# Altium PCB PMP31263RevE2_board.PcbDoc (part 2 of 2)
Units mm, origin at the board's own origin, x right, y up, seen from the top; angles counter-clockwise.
Board outline 111.13 x 148.59 mm, 4 copper layers (Top Layer, Layer 1, Layer 2, Bottom Layer), stack 0.603 mm thick; 138 components, 59 nets, 350 pads, 1544 vias.
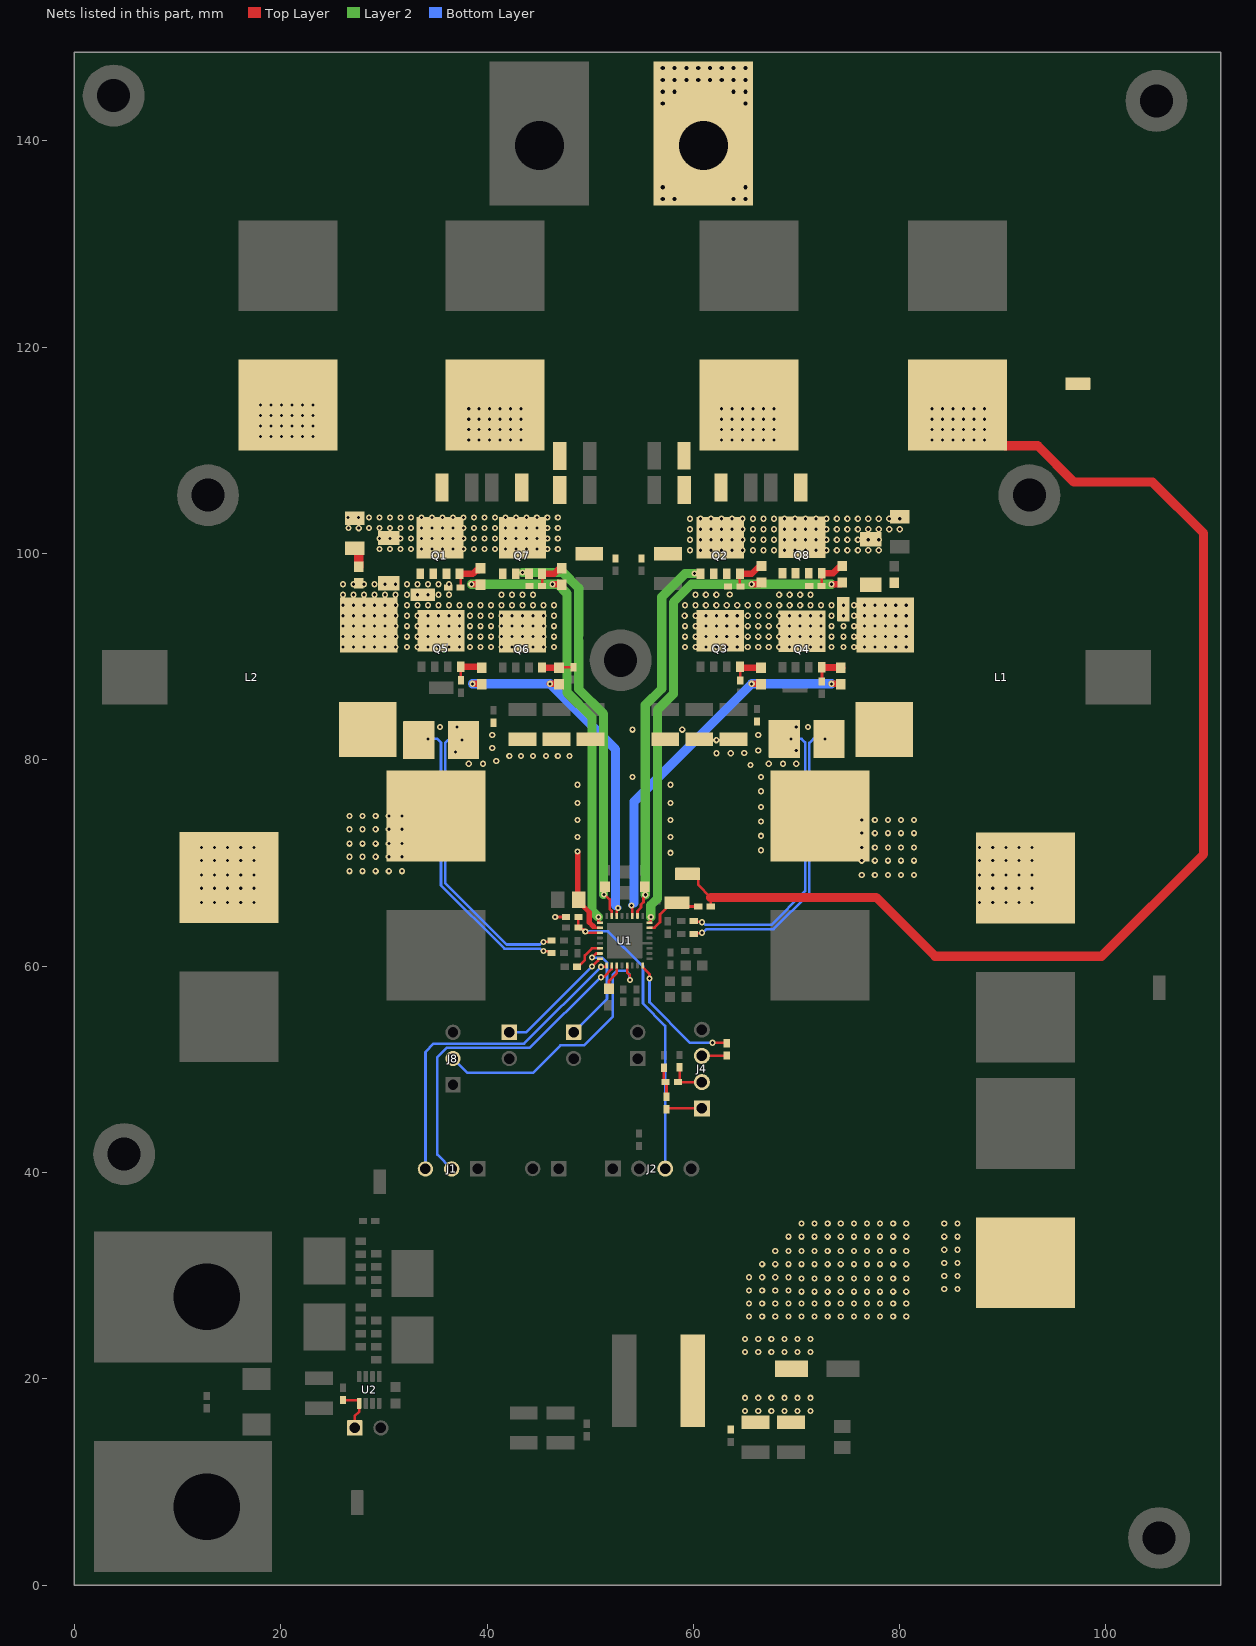
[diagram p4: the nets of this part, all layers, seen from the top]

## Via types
v1: diameter 0.6, hole 0.3, Top Layer to Bottom Layer, tented both sides, 1364 vias
v2: diameter 0.813, hole 0.406, Top Layer to Bottom Layer, 172 vias
v3: diameter 0.5, hole 0.2, Top Layer to Bottom Layer, 5 vias
v4: diameter 0.6/0.6/0.6/0.6 (per signal layer), hole 0.3, Top Layer to Bottom Layer, tented both sides, 2 vias
v5: diameter 0.6, hole 0.3, Top Layer to Bottom Layer, tented top, 1 vias

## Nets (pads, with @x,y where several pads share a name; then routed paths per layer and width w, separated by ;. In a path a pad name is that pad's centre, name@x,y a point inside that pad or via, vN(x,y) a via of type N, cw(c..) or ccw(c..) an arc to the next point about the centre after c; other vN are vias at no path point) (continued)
NetC47_1: C47.1 R33.1 | length 2
  Top Layer w0.635: R33.1@27.178,100.531 cw(c27.178,100.15) 27.45,100.417 ccw(c28.575,100.457) R33.1@27.559,99.973
  Top Layer w0.889: C47.1@27.559,98.717 R33.1@27.559,99.973
NetC52_1: C52.1 J4.2 R15.2 | length 3.8
  Top Layer w0.254: C52.1@58.674,50.2 58.674,48.93 R15.2@58.512,48.768 J4.2@60.833,48.768
NetC53_1: C53.1 R15.1 R18.1 | length 2.9
  Top Layer w0.254: C53.1@57.15,50.165 57.15,48.93 R15.1@57.312,48.768 57.404,48.676 R18.1@57.404,47.336
NetJ2_3: J2.3 R14.1 R17.2 U1.19 | length 30.8
  Top Layer w0.254: R14.1@48.86,64.77 R17.2@48.86,63.754 49.033,63.581 49.322,63.581 v1(49.53,63.373) 49.669,63.234 U1.19@50.94,63.234
  Bottom Layer w0.254: v1(49.53,63.373) 51.725,63.373 52.664,62.434 52.664,62.411 53.255,61.82 53.278,61.82 55.118,59.98 55.118,56.388 57.277,54.229 J2.3@57.277,40.386
NetJ3_1: J3.1 U1.24 | length 11.8
  Top Layer w0.254: v1(50.187,59.981) 50.767,60.561 50.767,60.732 50.769,60.734 U1.24@50.94,60.734
  Bottom Layer w0.254: J3.1@42.164,53.594 43.8,53.594 v1(50.187,59.981)
NetJ4_1: J4.1 R18.2 | length 3.5
  Top Layer w0.254: R18.2@57.404,46.136 57.496,46.228 J4.1@60.833,46.228
NetJ4_3: J4.3 R20.2 | length 2.5
  Top Layer w0.254: J4.3@60.833,51.308 63.081,51.308 R20.2@63.246,51.143
NetJ7_1: J7.1 R29.1 U2.1 | length 4.4
  Top Layer w0.254: R29.1@26.035,17.942 27.502,17.942 27.6,17.844 U2.1@27.6,17.623 27.6,16.805 27.178,16.383 J7.1@27.178,15.24
NetJ8_2: J8.2 U1.29 | length 26.4
  Top Layer w0.254: U1.29@53.59,60.084 53.59,59.403 53.848,59.145 v1(53.848,58.674)
  Bottom Layer w0.254: J8.2@36.703,51.054 38.1,49.657 44.45,49.657 47.117,52.324 49.403,52.324 52.197,55.118 52.197,59.182 52.578,59.563 53.467,59.563 53.782,59.248 53.782,58.74 v1(53.848,58.674)
NetJ9_1: J9.1 U1.23 | length 10.7
  Top Layer w0.254: v5(50.165,60.833) 50.564,61.232 50.938,61.232 U1.23@50.94,61.234
  Bottom Layer w0.254: J9.1@48.387,53.594 51.633,56.84 51.633,60.359 51.159,60.833 v5(50.165,60.833)
NetL1_2: L1.2 R3.1 R5.2 | length 29.1
  Top Layer w0.254: R5.2@60.036,63.119 60.1,63.182 60.77,63.182 v1(60.833,63.246)
  Bottom Layer w0.254: v1(60.833,63.246) 60.927,63.246 61.282,63.602 67.793,63.602 71.247,67.056 71.247,81.661 71.628,82.042 v1(72.771,82.042)
NetL2_1: L2.1 R4.2 R8.2 | length 29.8
  Top Layer w0.254: R4.2@33.141,82.042 v1(34.29,82.042) ; v1(45.466,61.468) 46.09,61.468 R8.2@46.262,61.296
  Bottom Layer w0.254: v1(34.29,82.042) 35.179,82.042 35.535,81.686 35.535,67.843 41.681,61.697 45.144,61.697 45.372,61.468 v1(45.466,61.468)
NetQ1_4: Q1.4 R27.1 R35.2 | length 3.6
  Top Layer w0.254: Q1.4@37.338,98.043 cw(c37.338,97.943) 37.438,97.943 R35.2@37.438,96.725
  Top Layer w0.635: Q1.4@37.338,98.043 38.64,98.043 39.004,98.407 39.212,98.407 39.37,98.565 R27.1@39.37,98.59
NetQ2_4: Q2.4 R21.2 R26.2 | length 3.7
  Top Layer w0.254: Q2.4@64.516,98.044 64.516,96.873 ccw(c64.564,96.873) R21.2@64.564,96.825
  Top Layer w0.635: Q2.4@64.516,98.044 65.658,98.044 66.237,98.623 66.445,98.623 66.603,98.78 R26.2@66.603,98.805
NetQ3_4: Q3.4 R9.2 R38.2 | length 3.2
  Top Layer w0.254: R38.2@64.543,87.7 64.543,88.907 cw(c64.574,88.907) Q3.4@64.574,88.938
  Top Layer w0.635: Q3.4@64.574,88.938 R9.2@66.548,88.938
NetQ4_4: Q4.4 R10.2 R39.1 | length 3.3
  Top Layer w0.254: R39.1@72.445,87.614 ccw(c72.445,87.645) 72.477,87.645 Q4.4@72.477,88.961
  Top Layer w0.635: Q4.4@72.477,88.961 74.412,88.961 R10.2@74.435,88.938
NetQ5_4: Q5.4 R12.2 R25.2 | length 3.5
  Top Layer w0.254: R25.2@37.465,87.722 Q5.4@37.465,89.026
  Top Layer w0.635: Q5.4@37.465,89.026 39.269,89.026 39.497,88.798 R12.2@39.497,88.773
NetQ6_4: Q6.4 R11.2 R24.2 | length 3.1
  Top Layer w0.254: R11.2@46.977,88.951 cw(c47.019,88.951) 47.019,88.992 R24.2@48.387,88.992
  Top Layer w0.635: Q6.4@45.339,88.963 45.352,88.951 R11.2@46.977,88.951
NetQ7_4: Q7.4 R2.1 R34.2 | length 3.3
  Top Layer w0.254: R34.2@45.323,96.857 45.339,96.857 Q7.4@45.339,98.043
  Top Layer w0.635: Q7.4@45.339,98.043 46.51,98.043 46.876,98.409 47.084,98.409 47.242,98.567 R2.1@47.242,98.592
NetQ8_4: Q8.4 R1.2 R36.2 | length 3.5
  Top Layer w0.254: R36.2@72.431,96.869 ccw(c72.431,96.891) 72.453,96.891 Q8.4@72.453,98.097
  Top Layer w0.635: Q8.4@72.453,98.097 73.544,98.097 74.07,98.623 74.278,98.623 74.435,98.78 R1.2@74.435,98.805
NetR1_1: R1.1 R26.1 U1.8 | length 50.3
  Top Layer w0.254: U1.8@55.74,64.234 55.878,64.234 55.88,64.236 v1(55.88,64.77)
  Top Layer w0.635: v1(65.659,97.028) 66.445,97.028 66.603,97.186 R26.1@66.603,97.205 ; v1(73.406,97.028) 74.278,97.028 74.435,97.186 R1.1@74.435,97.205
  Layer 2 w0.889: v1(55.88,64.77) 55.88,65.913 56.515,66.548 56.515,84.836 58.064,86.385 58.064,95.275 59.817,97.028 v1(73.406,97.028)
NetR2_2: R2.2 R27.2 U1.17 | length 44.8
  Top Layer w0.254: v1(50.8,64.77) 50.8,64.236 50.802,64.234 U1.17@50.94,64.234
  Top Layer w0.635: v1(38.481,97.028) 39.332,97.028 R27.2@39.37,96.99 ; v1(46.355,97.028) 47.205,97.028 R2.2@47.242,96.992
  Layer 2 w0.889: v1(38.481,97.028) v1(46.355,97.028) 46.863,97.028 47.752,96.139 47.752,86.538 50.165,84.125 50.165,65.405 v1(50.8,64.77)
NetR9_1: R9.1 R10.1 U1.11 | length 36.9
  Top Layer w0.254: v1(53.996,65.892) 53.996,65.798 54.09,65.704 U1.11@54.09,64.884
  Top Layer w0.635: v1(65.659,87.376) 66.51,87.376 R9.1@66.548,87.338 ; v1(73.406,87.376) 74.257,87.376 R10.1@74.295,87.338
  Bottom Layer w0.635: v1(53.996,65.892) 54.245,66.14
  Bottom Layer w0.889: 54.245,66.14 54.245,75.962 v1(65.659,87.376) v1(73.406,87.376)
NetR11_1: R11.1 R12.1 U1.14 | length 34.6
  Top Layer w0.254: U1.14@52.59,64.884 52.59,65.544 v1(52.705,65.659)
  Top Layer w0.635: v1(38.608,87.376) 39.459,87.376 R12.1@39.497,87.338 ; v1(46.101,87.376) 46.952,87.376 R11.1@46.99,87.338
  Bottom Layer w0.635: 52.451,65.913 v1(52.705,65.659)
  Bottom Layer w0.889: v1(38.608,87.376) v1(46.101,87.376) 52.451,81.026 52.451,65.913
NetR13_1: R13.1 TP2.1 U1.7 | length 6.4
  Top Layer w0.254: U1.7@55.74,63.734 55.742,63.736 56.237,63.736 56.769,64.268 56.769,65.024 58.293,66.548 TP2.1@58.293,66.562 ; TP2.1@58.42,66.167 58.801,65.786 R13.1@60.487,65.786
NetR19_2: R19.2 U1.27 | length 2.6
  Top Layer w0.254: R19.2@51.816,57.848 51.824,57.856 51.824,58.555 52.59,59.321 U1.27@52.59,60.084
NetR20_1: R20.1 U1.32 | length 13
  Top Layer w0.254: U1.32@55.09,60.084 55.09,59.913 55.753,59.25 v1(55.753,58.801) ; v1(61.849,52.578) 63.081,52.578 R20.1@63.246,52.743
  Bottom Layer w0.254: v1(55.753,58.801) 55.753,56.515 59.69,52.578 v1(61.849,52.578)
NetR37_1: R37.1 U1.22 | length 3.2
  Top Layer w0.254: R37.1@48.733,59.944 48.833,59.944 49.491,60.602 49.491,61.058 50.167,61.734 U1.22@50.94,61.734
SCL: J1.2 U1.26 | length 32.2
  Top Layer w0.254: v1(51.054,58.928) 51.12,58.994 51.367,58.994 52.09,59.717 U1.26@52.09,60.084
  Bottom Layer w0.254: J1.2@36.572,40.346 35.179,41.739 35.179,51.181 36.081,52.083 44.142,52.083 50.986,58.928 v1(51.054,58.928)
SDA: J1.3 U1.25 | length 32.5
  Top Layer w0.254: v1(51.054,59.944) 51.588,59.944 51.59,59.946 U1.25@51.59,60.084
  Bottom Layer w0.254: J1.3@34.032,40.346 34.032,51.685 34.837,52.49 43.6,52.49 v1(51.054,59.944)
SW1: C46.2 D3.2 L1.1 Q2.1 Q2.2 Q2.3 Q3.5 Q4.5 Q8.1 Q8.2 Q8.3 R21.1 R30.2 R36.1 TP3.1 U1.10 | length 36.8
  Top Layer w0.254: U1.10@54.59,64.884 54.59,65.358 54.931,65.699 54.931,65.972 54.999,66.04 55.172,66.213 55.172,66.661 55.347,66.835 v1(55.347,66.929) 55.347,67.66 R30.2@55.298,67.709
  Layer 2 w0.889: v1(55.347,66.929) 55.347,85.319 56.935,86.907 56.935,95.797 59.207,98.069 v1(60.118,98.069)
  other v1: 59.182,90.932 60.198,90.932 61.214,90.932 62.23,90.932 63.246,90.932 64.262,90.932 65.278,90.932 66.294,90.932 67.31,90.932 68.326,90.932 69.342,90.932 70.358,90.932 71.374,90.932 72.39,90.932 73.406,90.932 74.549,90.932 75.565,90.932 76.581,90.932 77.597,90.932 78.613,90.932 79.629,90.932 80.645,90.932 59.182,91.948 60.198,91.948 61.214,91.948 62.23,91.948 63.246,91.948 64.262,91.948 65.278,91.948 66.294,91.948 67.31,91.948 68.326,91.948 69.342,91.948 70.358,91.948 71.374,91.948 72.39,91.948 73.406,91.948 74.549,91.948 75.565,91.948 76.581,91.948 77.597,91.948 78.613,91.948 79.629,91.948 80.645,91.948 59.182,92.964 60.198,92.964 61.214,92.964 62.23,92.964 63.246,92.964 64.262,92.964 65.278,92.964 66.294,92.964 67.31,92.964 68.326,92.964 69.342,92.964 70.358,92.964 71.374,92.964 72.39,92.964 73.406,92.964 74.549,92.964 75.565,92.964 76.581,92.964 77.597,92.964 78.613,92.964 79.629,92.964 80.645,92.964 59.161,93.979 60.198,93.98 61.214,93.98 62.23,93.98 63.246,93.98 64.262,93.98 65.278,93.98 66.294,93.98 67.31,93.98 68.326,93.98 69.342,93.98 70.358,93.98 71.374,93.98 72.39,93.98 73.406,93.98 74.549,93.98 75.565,93.98 76.581,93.98 77.597,93.98 78.613,93.98 79.629,93.98 80.645,93.98 59.203,94.994 60.198,94.996 61.214,94.996 62.23,94.996 63.246,94.996 64.262,94.996 65.278,94.996 66.294,94.996 67.31,94.996 68.326,94.996 69.342,94.996 70.358,94.996 71.374,94.996 72.39,94.996 73.406,94.996 74.549,94.996 75.565,94.996 76.581,94.996 77.597,94.996 78.613,94.996 79.629,94.996 80.645,94.996 60.198,96.012 61.214,96.012 62.23,96.012 63.53,96.024 68.326,96.012 69.342,96.012 70.358,96.012 71.374,96.012
SW2: C47.2 D2.2 L2.2 Q1.1 Q1.2 Q1.3 Q5.5 Q6.5 Q7.1 Q7.2 Q7.3 R31.1 R34.1 R35.1 TP5.1 U1.15 | length 40
  Top Layer w0.254: R31.1@51.181,67.508 R31.1@51.181,67.602 ; v1(51.338,66.951) 51.338,67.594 R31.1@51.435,67.691 ; v1@51.435,66.929 51.881,66.483 51.881,66.04 51.881,65.83 51.892,65.819 51.892,65.557 52.09,65.36 ; U1.15@52.095,64.853 52.095,65.354
  Layer 2 w0.889: v1(43.434,98.171) 47.371,98.171 48.895,96.647 48.895,92.208 cw(c48.006,92.208) 48.892,92.137 ccw(c52.832,91.821) 48.892,91.503 cw(c48.006,91.434) 48.895,91.434 48.895,86.868 51.308,84.455 v1@51.308,66.951
  other v1: 26.035,90.932 27.051,90.932 28.067,90.932 29.083,90.932 30.099,90.932 31.115,90.932 32.258,90.932 33.274,90.932 34.29,90.932 35.306,90.932 36.322,90.932 37.338,90.932 38.354,90.932 39.37,90.932 40.386,90.932 41.402,90.932 42.418,90.932 43.434,90.932 44.45,90.932 45.466,90.932 46.482,90.932 26.035,91.948 27.051,91.948 28.067,91.948 29.083,91.948 30.099,91.948 31.115,91.948 32.258,91.948 33.274,91.948 34.29,91.948 35.306,91.948 36.322,91.948 37.338,91.948 38.354,91.948 39.37,91.948 40.386,91.948 41.402,91.948 42.418,91.948 43.434,91.948 44.45,91.948 45.466,91.948 46.482,91.948 26.035,92.964 27.051,92.964 28.067,92.964 29.083,92.964 30.099,92.964 31.115,92.964 32.258,92.964 33.274,92.964 34.29,92.964 35.306,92.964 36.322,92.964 37.338,92.964 38.354,92.964 39.37,92.964 40.386,92.964 41.402,92.964 42.418,92.964 43.434,92.964 44.45,92.964 45.466,92.964 46.482,92.964 26.035,93.98 27.051,93.98 28.067,93.98 29.083,93.98 30.099,93.98 31.115,93.98 32.258,93.98 33.274,93.98 34.29,93.98 35.306,93.98 36.322,93.98 37.338,93.98 38.354,93.98 39.37,93.98 40.386,93.98 41.402,93.98 42.418,93.98 43.434,93.98 44.45,93.98 45.466,93.98 46.482,93.98 26.035,94.996 27.051,94.996 28.067,94.996 29.083,94.996 30.099,94.996 31.115,94.996 32.258,94.996 33.274,94.996 34.29,94.996 35.306,94.996 36.322,94.996 37.338,94.996 38.354,94.996 39.37,94.996 40.386,94.996 41.402,94.996 42.418,94.996 43.434,94.996 44.45,94.996 45.466,94.996 46.482,94.996 26.035,96.012 27.051,96.012 28.067,96.012 29.083,96.012 30.099,96.012 31.115,96.012 32.258,96.012 33.274,96.012 34.29,96.012 35.306,96.012 36.322,96.012 41.402,96.012 42.418,96.012 43.434,96.012 44.45,96.012 26.035,97.028 27.051,97.028 28.067,97.028 29.083,97.028 30.099,97.028 31.115,97.028 32.258,97.028 33.274,97.028 34.29,97.028 35.306,97.028 36.322,97.028
Vboost: C16.1 C17.1 C18.1 C19.1 C20.1 C21.1 C22.1 C23.1 C24.1 C25.1 C48.1 C49.1 C50.1 C51.1 C54.1 C55.1 D2.1 D3.1 Q1.5 Q2.5 Q7.5 Q8.5 R13.2 R32.2 R33.2 T2.1 TP1.1 TP8.1 | length 125.5
  Top Layer w0.254: TP1.1@59.436,68.961 59.988,68.961 60.461,68.488 60.461,67.901 61.687,66.675 R13.2@61.687,65.786
  Top Layer w0.889: 61.687,66.675 77.724,66.675 83.439,60.96 99.568,60.96 109.474,70.866 109.474,101.981 104.521,106.934 96.903,106.934 93.384,110.452 90.237,110.452 88.819,111.87 C19.1@88.819,112.314 ; C19.1@86.082,113.924 C19.1@87.098,112.908 ; C19.1@87.012,113.838 C19.1@87.52,113.33 ; v1(88.236,110.998) 88.236,111.77 C19.1@87.098,112.908 ; C19.1@88.536,112.314 88.028,112.822 C19.1@87.52,113.33 ; C19.1@87.098,112.908 C19.1@85.598,114.408 86.442,114.408 C19.1@87.52,113.33
  other v1: 59.69,100.33 60.706,100.33 61.722,100.33 62.738,100.33 63.754,100.33 64.77,100.33 65.786,100.33 66.802,100.33 67.818,100.33 68.834,100.33 69.85,100.33 70.866,100.33 71.882,100.33 72.898,100.33 73.914,100.33 74.93,100.33 75.946,100.33 76.962,100.33 77.978,100.33 29.591,100.457 30.607,100.457 31.623,100.457 32.639,100.457 33.655,100.457 34.671,100.457 35.687,100.457 36.703,100.457 37.719,100.457 38.735,100.457 39.751,100.457 40.767,100.457 41.783,100.457 42.799,100.457 43.815,100.457 44.831,100.457 45.847,100.457 46.863,100.457 59.69,101.346 60.706,101.346 61.722,101.346 62.738,101.346 63.754,101.346 64.77,101.346 65.786,101.346 66.802,101.346 67.818,101.346 68.834,101.346 69.85,101.346 70.866,101.346 71.882,101.346 72.898,101.346 73.914,101.346 74.93,101.346 75.946,101.346 76.962,101.346 77.978,101.346 29.591,101.473 30.607,101.473 31.623,101.473 32.639,101.473 33.655,101.473 34.671,101.473 35.687,101.473 36.703,101.473 37.719,101.473 38.735,101.473 39.751,101.473 40.767,101.473 41.783,101.473 42.799,101.473 43.815,101.473 44.831,101.473 45.847,101.473 46.863,101.473 59.69,102.362 60.706,102.362 61.722,102.362 62.738,102.362 63.754,102.362 64.77,102.362 65.786,102.362 66.802,102.362 67.818,102.362 68.834,102.362 69.85,102.362 70.866,102.362 71.882,102.362 72.898,102.362 73.914,102.362 74.93,102.362 75.946,102.362 76.962,102.362 77.978,102.362 78.994,102.362 80.01,102.362 26.568,102.475 27.571,102.467 28.575,102.489 29.591,102.489 30.607,102.489 31.623,102.489 32.639,102.489 33.655,102.489 34.671,102.489 35.687,102.489 36.703,102.489 37.719,102.489 38.735,102.489 39.751,102.489 40.767,102.489 41.783,102.489 42.799,102.489 43.815,102.489 44.831,102.489 45.847,102.489 46.863,102.489 59.69,103.378 60.706,103.378 61.722,103.378 62.738,103.378 63.754,103.378 64.77,103.378 65.786,103.378 66.802,103.378 67.818,103.378 68.834,103.378 69.85,103.378 70.866,103.378 71.882,103.378 72.898,103.378 73.914,103.378 74.93,103.378 75.946,103.378 76.962,103.378 77.978,103.378 78.994,103.378 80.01,103.378 26.543,103.505 27.559,103.505 28.575,103.505 29.591,103.505 30.607,103.505 31.623,103.505 32.639,103.505 33.655,103.505 34.671,103.505 35.687,103.505 36.703,103.505 37.719,103.505 38.735,103.505 39.751,103.505 40.767,103.505 41.783,103.505 42.799,103.505 43.815,103.505 44.831,103.505 45.847,103.505 46.863,103.505 38.227,110.998 39.243,110.998 40.259,110.998 41.275,110.998 42.291,110.998 43.307,110.998 62.738,110.998 63.754,110.998 64.77,110.998 65.786,110.998 66.802,110.998 67.818,110.998 83.156,110.998 84.172,110.998 85.188,110.998 86.204,110.998 87.22,110.998 18.034,111.36 19.05,111.36 20.066,111.36 21.082,111.36 22.098,111.36 23.114,111.36 38.227,112.014 39.243,112.014 40.259,112.014 41.275,112.014 42.291,112.014 43.307,112.014 62.738,112.014 63.754,112.014 64.77,112.014 65.786,112.014 66.802,112.014 67.818,112.014 83.156,112.014 84.172,112.014 85.188,112.014 86.204,112.014 87.22,112.014 88.236,112.014 18.034,112.376 19.05,112.376 20.066,112.376 21.082,112.376 22.098,112.376 23.114,112.376 38.227,113.03 39.243,113.03 40.259,113.03 41.275,113.03 42.291,113.03 43.307,113.03 62.738,113.03 63.754,113.03 64.77,113.03 65.786,113.03 66.802,113.03 67.818,113.03 83.156,113.03 84.172,113.03 85.188,113.03 86.204,113.03 87.22,113.03 88.236,113.03 18.034,113.392 19.05,113.392 20.066,113.392 21.082,113.392 22.098,113.392 23.114,113.392 38.227,114.046 39.243,114.046 40.259,114.046 41.275,114.046 42.291,114.046 43.307,114.046 62.738,114.046 63.754,114.046 64.77,114.046 65.786,114.046 66.802,114.046 67.818,114.046 83.156,114.046 84.172,114.046 85.188,114.046 86.204,114.046 87.22,114.046 88.236,114.046 18.034,114.408 19.05,114.408 20.066,114.408 21.082,114.408 22.098,114.408 23.114,114.408
  other v2: 57.046,134.366 58.189,134.366 63.904,134.366 65.047,134.366 57.046,135.509 65.047,135.509 57.046,143.637 65.047,143.637 57.046,144.78 58.189,144.78 63.904,144.78 65.047,144.78 57.046,145.923 58.189,145.923 59.332,145.923 60.475,145.923 61.618,145.923 62.761,145.923 63.904,145.923 65.047,145.923 57.046,147.066 58.189,147.066 59.332,147.066 60.475,147.066 61.618,147.066 62.761,147.066 63.904,147.066 65.047,147.066
VIN_FLT: C1.1 C2.1 C3.1 C4.1 C5.1 C6.1 C7.1 C8.1 C9.1 C10.1 C11.1 C12.1 C13.1 C14.1 C15.1 C30.1 C37.1 C43.1 L3.2 R3.2 R4.1 R6.2 R7.2 R14.2 U1.18 | length 68.9
  Top Layer w0.254: R4.1@38.614,81.915 R4.1@38.741,82.042 ; v1(45.466,62.357) 46.136,62.357 R7.2@46.263,62.484 ; v1(46.609,64.77) R14.2@47.66,64.77 ; 50.272,63.734 U1.18@50.94,63.734 ; R6.2@60.036,64.389 60.1,64.325 60.77,64.325 v1(60.833,64.262)
  Top Layer w0.508: v1(48.768,71.12) 48.786,71.102 48.786,66.967 48.62,66.802 48.514,66.802 C30.1@48.895,66.421 48.895,66.256 49.911,65.24 49.911,64.262 50.292,63.881
  Top Layer w0.635: v4(37.592,81.915) R4.1@38.614,81.915 ; R3.2@68.193,82.042 v4(69.469,82.042)
  Bottom Layer w0.254: v4(37.592,81.915) 36.195,81.915 35.941,81.661 35.941,68.072 41.91,62.103 45.118,62.103 45.372,62.357 v1(45.466,62.357) ; v1(60.833,64.262) 60.927,64.262 61.181,64.008 67.564,64.008 70.841,67.285 70.841,81.686 70.485,82.042 v4(69.469,82.042)
  other v1: 65.024,16.891 66.294,16.891 67.564,16.891 68.834,16.891 70.104,16.891 71.374,16.891 65.024,18.161 66.294,18.161 67.564,18.161 68.834,18.161 70.104,18.161 71.374,18.161 65.024,22.606 66.294,22.606 67.564,22.606 68.834,22.606 70.104,22.606 71.374,22.606 65.024,23.876 66.294,23.876 67.564,23.876 68.834,23.876 70.104,23.876 71.374,23.876 65.405,26.035 66.675,26.035 67.945,26.035 69.215,26.035 70.485,26.035 71.755,26.035 73.025,26.035 74.295,26.035 75.565,26.035 76.835,26.035 78.105,26.035 79.375,26.035 80.645,26.035 65.405,27.305 66.675,27.305 67.945,27.305 69.215,27.305 70.485,27.305 71.755,27.305 73.025,27.305 74.295,27.305 75.565,27.305 76.835,27.305 78.105,27.305 79.375,27.305 80.645,27.305 70.485,28.448 71.755,28.448 73.025,28.448 74.295,28.448 75.565,28.448 76.835,28.448 78.105,28.448 79.375,28.448 80.645,28.448 65.405,28.575 66.675,28.575 67.945,28.575 69.215,28.575 84.328,28.702 85.598,28.702 70.485,29.718 71.755,29.718 73.025,29.718 74.295,29.718 75.565,29.718 76.835,29.718 78.105,29.718 79.375,29.718 80.645,29.718 65.405,29.845 66.675,29.845 67.945,29.845 69.215,29.845 84.328,29.972 85.598,29.972 66.675,31.115 67.945,31.115 69.215,31.115 70.485,31.115 71.755,31.115 73.025,31.115 74.295,31.115 75.565,31.115 76.835,31.115 78.105,31.115 79.375,31.115 80.645,31.115 84.328,31.242 85.598,31.242 67.945,32.385 69.215,32.385 70.485,32.385 71.755,32.385 73.025,32.385 74.295,32.385 75.565,32.385 76.835,32.385 78.105,32.385 79.375,32.385 80.645,32.385 84.328,32.512 85.598,32.512 69.215,33.782 70.485,33.782 71.755,33.782 73.025,33.782 74.295,33.782 75.565,33.782 76.835,33.782 78.105,33.782 79.375,33.782 80.645,33.782 84.328,33.782 85.598,33.782 70.485,35.052 71.755,35.052 73.025,35.052 74.295,35.052 75.565,35.052 76.835,35.052 78.105,35.052 79.375,35.052 80.645,35.052 84.328,35.052 85.598,35.052 12.319,66.167 13.589,66.167 14.859,66.167 16.129,66.167 17.399,66.167 87.757,66.167 89.027,66.167 90.297,66.167 91.567,66.167 92.837,66.167 12.319,67.564 13.589,67.564 14.859,67.564 16.129,67.564 17.399,67.564 87.757,67.564 89.027,67.564 90.297,67.564 91.567,67.564 92.837,67.564 12.319,68.834 13.589,68.834 14.859,68.834 16.129,68.834 17.399,68.834 76.327,68.834 77.597,68.834 78.867,68.834 80.137,68.834 81.407,68.834 87.757,68.834 89.027,68.834 90.297,68.834 91.567,68.834 92.837,68.834 26.67,69.215 27.94,69.215 29.21,69.215 30.48,69.215 31.75,69.215 12.319,70.231 13.589,70.231 14.859,70.231 16.129,70.231 17.399,70.231 76.327,70.231 77.597,70.231 78.867,70.231 80.137,70.231 81.407,70.231 87.757,70.231 89.027,70.231 90.297,70.231 91.567,70.231 92.837,70.231 26.67,70.612 27.94,70.612 29.21,70.612 30.48,70.612 31.75,70.612 57.785,70.993 66.548,71.247 12.319,71.501 13.589,71.501 14.859,71.501 16.129,71.501 17.399,71.501 76.327,71.501 77.597,71.501 78.867,71.501 80.137,71.501 81.407,71.501 87.757,71.501 89.027,71.501 90.297,71.501 91.567,71.501 92.837,71.501 26.67,71.882 27.94,71.882 29.21,71.882 30.48,71.882 31.75,71.882 48.768,72.517 57.785,72.517 66.548,72.644 76.327,72.898 77.597,72.898 78.867,72.898 80.137,72.898 81.407,72.898 26.67,73.279 27.94,73.279 29.21,73.279 30.48,73.279 31.75,73.279 66.548,74.041 48.768,74.168 57.785,74.168 76.327,74.168 77.597,74.168 78.867,74.168 80.137,74.168 81.407,74.168 26.67,74.549 27.94,74.549 29.21,74.549 30.48,74.549 31.75,74.549 66.548,75.438 48.768,75.819 57.785,75.819 66.548,76.962 48.768,77.597 57.785,77.597 54.102,78.359 66.548,78.359 65.532,79.502 38.227,79.629 39.624,79.629 67.31,79.629 68.707,79.629 69.977,79.629 40.894,79.883 42.164,80.391 43.307,80.391 44.45,80.391 45.72,80.391 46.863,80.391 48.006,80.391 62.244,80.649 63.627,80.645 64.936,80.657 36.957,80.772 66.294,80.899 69.977,80.899 40.513,81.153 62.23,81.915 40.513,82.423 66.294,82.423 54.102,82.931 58.928,82.931 35.433,83.185 37.084,83.185 69.977,83.185 71.12,83.185
pads on no net: L1.3 L2.3 U2.3

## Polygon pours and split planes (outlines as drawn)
GND on Top Layer "NONET_L01_P-001" (solid, pour order 51): 21.412,38.71 25.197,42.494 29.769,42.494 33.553,38.71 110.363,38.71 110.363,59.69 82.931,59.69 76.962,65.659 50.038,65.659 48.514,67.183 45.339,67.183 43.815,65.659 30.226,65.659 24.13,59.563 1.397,59.563 1.397,38.71
NetC45_1 on Top Layer "NONET_L01_P-001" (solid, pour order 37): 27.356,32.588 27.178,32.41 27.178,22.733 27.305,22.606 29.718,22.606 29.845,22.733 29.845,32.461 29.718,32.588
GND on Top Layer "NONET_L01_P-001" (solid, pour order 17): 41.529,84.074 41.134,84.469 36.054,84.469 32.004,88.519 32.004,89.408 32.258,89.662 46.863,89.662 47.498,90.297 47.498,95.504 48.514,96.52 48.514,98.298 48.768,98.552 58.674,98.552 59.055,98.171 59.055,96.52 58.039,95.504 58.039,90.297 58.674,89.662 71.755,89.662 72.263,89.154 72.263,85.217 71.755,84.709 65.726,84.709 65.091,84.074
SW2 on Top Layer "NONET_L01_P-001" (solid, pour order 3): 30.353,90.424 30.353,98.552 36.449,98.552 cw(c36.449,98.425) 36.576,98.425 36.576,96.774 ccw(c37.592,96.774) 37.592,95.758 39.497,95.758 ccw(c39.497,97.155) 40.894,97.155 40.894,98.425 cw(c41.148,98.425) 41.148,98.679 44.323,98.679 cw(c44.323,98.425) 44.577,98.425 44.577,96.647 ccw(c45.593,96.774) 45.72,95.758 cw(c45.812,94.658) 46.863,94.996 46.863,90.932 cw(c46.355,90.932) 46.355,90.424
Vboost on Top Layer "NONET_L01_P-001" (solid, pour order 10): 36.449,99.441 25.654,99.441 15.367,109.728 15.367,118.491 36.449,118.491
SW2 on Top Layer "NONET_L01_P-001" (solid, pour order 76): 31.242,98.552 30.489,98.552 ccw(c30.489,96.384) 28.956,97.917 cw(c28.343,98.53) 28.343,97.663 26.457,97.663 ccw(c26.457,96.574) 25.369,96.574 25.369,90.862 ccw(c25.807,90.862) 25.807,90.424 31.115,90.424 ccw(c31.115,90.551) 31.242,90.551
VIN_FLT on Top Layer "NONET_L01_P-001" (solid, pour order 48): 65.405,73.914 104.267,73.914 105.029,73.152 105.029,67.056 98.933,60.96 83.185,60.96 77.724,66.421 64.897,66.421 60.833,70.485
GND on Top Layer "NONET_L01_P-001" (solid, pour order 47): 98.044,147.828 110.363,135.509 110.363,120.777 109.728,120.142 15.748,120.142 14.035,118.429 14.035,107.507 10.795,104.267 3.81,104.267 1.778,106.299 1.778,134.493 15.113,147.828
Vboost on Top Layer "NONET_L01_P-001" (solid, pour order 19): 48.514,110.109 48.514,111.252 49.022,111.76 57.277,111.76 57.658,111.379 57.658,104.14 57.023,103.505 57.023,103.251 63.5,103.251 63.983,103.734 63.983,118.745 45.339,118.745 45.339,110.109
VIN_FLT on Top Layer "NONET_L01_P-001" (solid, pour order 18): 40.894,83.82 41.402,83.312 65.151,83.312 65.786,83.947 71.755,83.947 72.136,83.566 72.136,80.01 72.898,79.248 76.835,79.248 83.185,72.898 83.185,70.231 40.259,70.231 30.353,70.231 29.591,70.993 29.591,78.867 29.972,79.248 34.163,79.248 34.798,79.883 34.798,83.439 35.179,83.82
NetL2_1 on Top Layer "NONET_L01_P-001" (solid, pour order 15): 31.623,87.63 34.29,84.963 34.29,80.264 33.909,79.883 25.273,79.883 24.892,80.264 24.892,87.249 25.273,87.63
Vboost on Top Layer "NONET_L01_P-001" (solid, pour order 8): 35.814,99.441 37.973,99.441 38.65,99.949 39.963,99.949 40.64,99.441 45.974,99.441 46.482,99.949 47.879,99.949 48.514,99.314 65.405,99.314 66.04,99.949 67.183,99.949 67.818,99.314 72.898,99.314 73.533,99.949 82.169,99.949 98.425,116.205 98.425,118.491 69.088,118.491 69.088,104.394 68.453,103.759 53.721,103.759 35.814,103.759
GND on Top Layer "NONET_L01_P-001" (solid, pour order 5): 68.326,108.204 cw(c68.326,108.077) 68.453,108.077 68.453,104.775 cw(c68.326,104.775) 68.326,104.648 64.77,104.648 cw(c64.77,104.775) 64.643,104.775 64.643,108.077 cw(c64.77,108.077) 64.77,108.204
GND on Top Layer "NONET_L01_P-001" (solid, pour order 0): 56.896,111.125 cw(c56.896,110.871) 57.15,110.871 57.15,104.521 cw(c56.897,104.52) 56.896,104.267 55.372,104.267 cw(c55.372,104.521) 55.118,104.521 55.118,110.871 cw(c55.372,110.871) 55.372,111.125
Vboost on Top Layer "NONET_L01_P-001" (solid, pour order 11): 37.465,104.14 41.783,104.14 42.037,104.394 42.037,108.458 41.656,108.839 40.259,108.839 40.259,110.363 41.021,111.125 48.514,111.125 48.514,104.14 50.673,101.981 37.465,101.981
Vboost on Top Layer "NONET_L01_P-001" (solid, pour order 12): 40.513,108.839 37.211,108.839 36.83,108.458 36.83,104.521 37.211,104.14 37.465,104.14 37.465,103.124 35.687,103.124 35.687,110.363 36.068,110.744 40.64,110.744
NetL1_2 on Top Layer "NONET_L01_P-001" (solid, pour order 16): 76.581,87.63 72.671,83.72 72.671,80.264 73.052,79.883 81.688,79.883 82.069,80.264 82.069,87.249 81.688,87.63
Vboost on Top Layer "NONET_L01_P-001" (solid, pour order 54): 109.728,119.253 110.363,118.618 110.363,108.458 109.728,107.823 87.249,107.823 79.502,115.57 15.367,115.57 15.367,118.872 15.748,119.253
VIN_FLT on Top Layer "NONET_L01_P-001" (solid, pour order 65): 69.85,35.687 58.801,24.638 58.801,15.24 59.055,14.986 71.12,14.986 71.882,15.748 71.882,21.971 72.898,22.987 93.472,22.987 97.409,26.924 97.409,35.306 97.028,35.687
GND on Top Layer "NONET_L01_P-001" (solid, pour order 66): 1.397,16.51 2.159,17.272 21.336,17.272 21.971,17.907 32.766,17.907 36.068,14.605 50.038,14.605 52.07,12.573 61.849,12.573 63.246,13.97 76.2,13.97 76.835,14.605 76.835,21.59 77.343,22.098 93.98,22.098 98.171,26.289 98.171,35.56 96.266,37.465 96.266,38.735 110.363,38.735 110.363,3.302 108.077,1.016 2.032,1.016 1.397,1.651
SW1 on Top Layer "NONET_L01_P-001" (solid, pour order 1): 81.407,90.424 ccw(c81.407,90.678) 81.661,90.678 81.661,95.631 ccw(c81.153,95.631) 81.153,96.139 72.263,96.139 cw(c72.263,96.774) 71.628,96.774 71.628,98.552 ccw(c71.501,98.552) 71.501,98.679 68.326,98.679 ccw(c68.326,98.425) 68.072,98.425 68.072,97.155 cw(c66.802,97.155) 66.802,95.885 64.643,95.885 cw(c64.579,96.71) 63.754,96.647 63.754,98.552 ccw(c63.627,98.552) 63.627,98.679 60.198,98.679 ccw(c60.198,98.298) 59.817,98.298 59.817,96.139 cw(c59.182,96.139) 59.182,95.504 ccw(c59.182,94.996) 58.674,94.996 58.674,90.932 ccw(c59.182,90.932) 59.182,90.424
Vboost on Top Layer "NONET_L01_P-001" (solid, pour order 14): 70.358,110.744 70.358,108.458 69.088,108.458 68.707,108.839 64.389,108.839 63.627,108.077 62.738,108.077 62.738,110.744
Vboost on Top Layer "NONET_L01_P-001" (solid, pour order 20): 69.018,104.092 64.31,104.092 63.373,105.029 63.373,103.378 68.961,103.378 68.961,103.489 69.018,103.547
AGND on Top Layer "NONET_L01_P-001" (solid, pour order 22): 58.547,57.785 57.912,57.15 50.8,57.15 48.26,59.69 48.26,63.881 48.006,64.135 45.085,64.135 44.45,63.5 44.45,59.055 52.578,50.927 59.182,50.927 62.103,53.848 62.103,61.849 61.468,62.484 58.547,62.484
VIN_FLT on Top Layer "NONET_L01_P-001" (solid, pour order 30): 1.524,73.724 1.524,60.452 24.13,60.452 29.972,66.294 43.561,66.294 47.879,70.612 47.879,77.724 46.355,79.248 29.972,79.248 24.448,73.724
NetC40_1 on Top Layer "NONET_L01_P-001" (solid, pour order 38): 36.913,15.411 31.877,20.447 31.287,20.447 30.608,21.126 30.608,34.121 30.952,34.442 52.629,34.442 54.738,32.333 54.738,15.665 54.484,15.411
NetC38_1 on Top Layer "NONET_L01_P-001" (solid, pour order 57): 19.685,34.417 25.73,40.462 30.353,40.462 30.607,40.208 30.607,37.922 29.413,36.728 26.899,36.728 26.416,36.246 26.416,19.431 26.67,19.177 26.416,18.923 21.717,18.923 20.798,18.004 2.062,18.004 1.397,18.669 1.397,34.036 1.778,34.417
SW1 on Top Layer "NONET_L01_P-001" (solid, pour order 75): 81.661,95.377 ccw(c79.248,95.377) 79.248,97.79 76.327,97.79 ccw(c76.327,97.409) 75.946,97.409 75.946,97.155 cw(c74.93,97.155) 74.93,96.139 74.93,95.377
GND on Top Layer "NONET_L01_P-001" (solid, pour order 70): 105.918,58.928 99.822,58.928 99.822,60.706 105.918,66.802 105.918,106.172 110.363,106.172 110.363,58.928
Vboost on Top Layer "NONET_L01_P-001" (solid, pour order 21): 50.8,112.014 51.562,111.252 51.562,104.14 51.054,103.632 55.245,103.632 54.61,104.267 54.61,111.379 55.245,112.014
GND on Top Layer "NONET_L01_P-001" (solid, pour order 6): 50.8,111.062 cw(c50.8,110.808) 51.054,110.808 51.054,104.584 cw(c50.674,104.584) 50.673,104.204 49.403,104.204 cw(c49.403,104.584) 49.022,104.584 49.022,110.808 cw(c49.276,110.808) 49.276,111.062
GND on Top Layer "NONET_L01_P-001" (solid, pour order 4): 41.275,108.204 cw(c41.275,108.077) 41.402,108.077 41.402,104.775 cw(c41.275,104.775) 41.275,104.648 37.719,104.648 cw(c37.719,104.775) 37.592,104.775 37.592,108.077 cw(c37.719,108.077) 37.719,108.204
VIN_FLT on Bottom Layer "NONET_L01_P-001" (solid, pour order 55): 109.347,83.693 110.236,82.804 110.236,3.175 107.95,0.889 65.278,0.889 64.643,1.524 64.643,26.543 54.229,36.957 29.591,36.957 27.813,38.735 2.159,38.735 1.397,39.497 1.397,82.55 2.54,83.693
GND on Bottom Layer "NONET_L01_P-001" (solid, pour order 79): 13.716,110.236 13.716,114.046 33.401,133.731 49.911,133.731 49.911,147.701 15.24,147.701 1.27,133.731 1.397,133.604 1.397,110.236
GND on Bottom Layer "NONET_L01_P-001" (solid, pour order 53): 57.531,98.679 57.912,98.298 57.912,88.9 58.674,88.138 63.627,88.138 63.881,87.884 63.881,86.741 61.595,84.455 50.927,84.455 48.768,86.614 48.768,98.171 49.276,98.679
SW1 on Bottom Layer "NONET_L01_P-001" (solid, pour order 28): 59.009,98.446 ccw(c59.009,97.938) 58.501,97.938 58.501,89.408 ccw(c59.009,89.408) 59.009,88.9 81.428,88.9 ccw(c81.441,89.501) 82.042,89.514 82.042,97.938 ccw(c81.475,97.877) 81.428,98.446
GND on Bottom Layer "NONET_L01_P-001" (solid, pour order 73): 1.016,13.843 1.016,16.637 1.524,17.145 28.956,17.145 31.75,14.351 49.657,14.351 51.689,12.319 63.119,12.319 63.5,11.938 63.5,1.651 62.738,0.889 1.905,0.889 1.016,1.778
GND on Bottom Layer "NONET_L01_P-001" (solid, pour order 72): 109.22,99.06 110.236,98.044 110.236,85.344 109.347,84.455 102.997,84.455 64.77,84.455 64.516,84.709 64.516,85.09 66.167,86.741 73.914,86.741 75.311,88.138 82.55,88.138 83.185,88.773 83.185,98.171 84.074,99.06
GND on Bottom Layer "NONET_L01_P-001" (solid, pour order 71): 2.54,84.455 1.397,85.598 1.397,133.096 13.741,133.096 13.741,100.559 15.24,99.06 22.352,99.06 22.987,98.425 22.987,88.773 23.495,88.265 36.576,88.265 38.227,86.614 45.847,86.614 46.609,85.852 46.609,84.709 46.355,84.455
Vboost on Bottom Layer "NONET_L01_P-001" (solid, pour order 46): 109.22,99.695 110.236,100.711 110.236,131.572 94.361,147.447 50.546,147.447 50.546,133.223 34.29,133.223 14.351,113.284 14.351,101.6 16.256,99.695
NetC40_1 on Bottom Layer "NONET_L01_P-001" (solid, pour order 39): 31.96,15.411 28.829,18.542 28.829,32.436 30.861,34.468 52.629,34.468 54.738,32.358 54.738,15.665 54.484,15.411
NetC38_1 on Bottom Layer "NONET_L01_P-001" (solid, pour order 36): 1.016,18.288 1.397,17.907 19.431,17.907 20.066,18.542 26.545,18.542 27.051,19.048 27.051,32.893 25.273,34.671 1.651,34.671 1.016,34.036
SW2 on Bottom Layer "NONET_L01_P-001" (solid, pour order 29): 24.721,98.448 ccw(c24.721,97.94) 24.213,97.94 24.213,89.411 ccw(c24.721,89.41) 24.721,88.903 47.14,88.903 ccw(c47.153,89.504) 47.754,89.517 47.754,97.94 ccw(c47.187,97.88) 47.14,98.448
VIN_FLT on Layer 2 "NONET_L01_P-001" (solid, pour order 56): 72.517,83.693 86.106,70.104 86.106,28.067 73.787,15.748 65.151,15.748 64.643,16.256 64.643,26.543 54.127,37.059 29.362,37.059 24.638,41.783 24.638,74.295 34.036,83.693
GND on Layer 2 "NONET_L01_P-001" (solid, pour order 61): 2.667,84.455 1.397,85.725 1.397,134.112 14.859,147.574 93.98,147.574 110.363,131.191 110.363,84.455
GND on Layer 2 "NONET_L01_P-001" (solid, pour order 67): 86.868,42.132 86.868,27.686 73.66,14.478 65.151,14.478 63.119,12.446 51.435,12.446 49.403,14.478 31.75,14.478 28.448,17.78 28.448,20.955 28.44,20.955 28.237,21.158 28.033,21.158 27.991,21.116 27.991,18.466 27.686,18.161 21.463,18.161 20.574,17.272 2.286,17.272 1.397,16.383 1.397,1.651 1.905,1.143 108.077,1.143 109.855,2.921 109.855,42.178
GND on Layer 2 "NONET_L01_P-001" (solid, pour order 63): 35.298,85.09 34.417,85.09 23.495,74.168 23.495,40.386 21.844,38.735 3.175,38.735 1.397,40.513 1.397,86.868 35.179,86.868
NetC38_1 on Layer 2 "NONET_L01_P-001" (solid, pour order 68): 1.379,34.344 1.125,34.09 1.125,18.85 2.141,17.834 19.54,17.834 20.683,18.977 26.017,18.977 26.779,19.739 26.779,33.419 25.854,34.344
GND on Layer 2 "NONET_L01_P-001" (solid, pour order 62): 71.882,84.709 72.517,84.709 86.995,70.231 86.995,40.513 87.63,39.878 109.855,39.878 109.855,87.249 71.882,87.249
SW2 on Layer 2 "NONET_L01_P-001" (solid, pour order 60): 42.426,96.312 37.673,96.312 cw(c37.673,97.028) 36.957,97.028 ccw(c36.576,97.028) 36.576,97.409 26.035,97.409 ccw(c26.035,96.901) 25.527,96.901 25.527,90.932 ccw(c26.035,90.932) 26.035,90.424 46.384,90.424 ccw(c46.384,90.844) 46.804,90.844 46.804,95.055 ccw(c46.482,95.055) 46.482,95.377 45.847,95.377 cw(c45.847,96.012) 45.212,96.012 ccw(c44.917,96.012) 44.917,96.307 44.179,96.307
Vboost on Layer 2 "NONET_L01_P-001" (solid, pour order 59): 46.863,104.013 cw(c46.863,103.632) 47.244,103.632 47.244,100.457 cw(c46.863,100.457) 46.863,100.076 26.416,100.076 cw(c26.416,100.457) 26.035,100.457 26.035,103.759 cw(c26.289,103.759) 26.289,104.013
Vboost on Layer 2 "NONET_L01_P-001" (solid, pour order 58): 80.01,103.886 cw(c80.01,103.505) 80.391,103.505 80.391,100.33 cw(c80.01,100.33) 80.01,99.949 59.563,99.949 cw(c59.563,100.33) 59.182,100.33 59.182,103.632 cw(c59.436,103.632) 59.436,103.886
SW1 on Layer 2 "NONET_L01_P-001" (solid, pour order 45): 58.87,90.932 58.87,90.863 ccw(c59.182,90.863) 59.182,90.551 80.772,90.551 ccw(c80.772,90.932) 81.153,90.932 81.153,94.996 ccw(c79.883,94.996) 79.887,96.266 60.093,96.315 59.052,95.313 ccw(c59.354,94.931) 58.87,94.987 58.87,94.597
NetC40_1 on Layer 2 "NONET_L01_P-001" (solid, pour order 33): 31.96,15.411 28.829,18.542 28.829,32.461 30.81,34.442 52.578,34.442 54.738,32.282 54.738,15.665 54.484,15.411
NetC40_1 on Layer 1 "NONET_L01_P-001" (solid, pour order 31): 31.96,15.411 29.083,18.288 29.083,32.639 30.963,34.519 52.553,34.519 54.738,32.333 54.738,15.665 54.484,15.411
GND on Layer 1 "NONET_L01_P-001" (solid, pour order 43): 110.363,110.109 110.363,34.414 60.115,34.322 55.702,38.735 1.397,38.735 1.397,110.109
GND on Layer 1 "NONET_L01_P-001" (solid, pour order 78): 33.147,133.731 16.002,116.586 16.002,110.871 17.526,109.347 1.397,109.347 1.397,134.112 14.986,147.701 49.911,147.701 49.911,133.731
Vboost on Layer 1 "NONET_L01_P-001" (solid, pour order 77): 108.204,110.617 109.982,112.395 109.982,131.826 94.107,147.701 50.419,147.701 50.419,133.223 33.655,133.223 16.637,116.205 16.637,111.506 17.526,110.617
GND on Layer 1 "NONET_L01_P-001" (solid, pour order 74): 56.014,38.238 67.19,27.062 67.19,13.981 65.539,12.33 51.442,12.33 49.41,14.362 31.757,14.362 28.455,17.664 28.455,20.839 28.447,20.839 28.244,21.042 28.04,21.042 27.998,21 27.998,18.35 27.693,18.045 21.47,18.045 20.581,17.156 2.293,17.156 1.404,16.267 1.404,1.535 1.912,1.027 108.084,1.027 110.363,3.306 110.363,38.345
NetC38_1 on Layer 1 "NONET_L01_P-001" (solid, pour order 69): 1.379,34.344 1.125,34.09 1.125,18.85 2.141,17.834 19.54,17.834 20.683,18.977 26.017,18.977 26.779,19.739 26.779,33.292 25.727,34.344

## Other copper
Layer 1:
  region net SW1: 59.182,90.551 cw(c59.182,90.932) 58.801,90.932 58.801,94.742 cw(c60.452,94.742) 60.452,96.393 79.629,96.393 cw(c79.629,94.996) 81.026,94.996 81.026,90.932 cw(c80.645,90.932) 80.645,90.551
  region net SW2: 46.863,94.996 ccw(c45.466,94.996) 45.466,96.393 38.227,96.393 cw(c38.227,97.155) 37.465,97.155 ccw(c37.211,97.155) 37.211,97.409 26.162,97.409 ccw(c26.162,96.901) 25.654,96.901 25.654,91.059 ccw(c26.162,91.059) 26.162,90.551 46.355,90.551 ccw(c46.355,91.059) 46.863,91.059
  pour cut-out: 65.384,90.124 80.98,90.124 ccw(c80.98,90.805) 81.661,90.805 81.661,98.171 ccw(c81.153,98.171) 81.153,98.679 58.801,98.679 ccw(c58.801,98.171) 58.293,98.171 58.293,90.805 ccw(c58.928,90.805) 58.928,90.17
  pour cut-out: 31.221,90.124 46.817,90.124 ccw(c46.817,90.805) 47.498,90.805 47.498,98.171 ccw(c46.99,98.171) 46.99,98.679 24.638,98.679 ccw(c24.638,98.171) 24.13,98.171 24.13,90.805 ccw(c24.765,90.805) 24.765,90.17

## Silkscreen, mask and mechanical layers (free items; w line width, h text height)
Top Overlay:
  lines w0.254: 37.973,95.758 38.735,94.996 ; 95.123,11.557 cw(c96.139,11.557) 96.139,12.573 96.266,12.573 ; 89.789,11.43 89.789,17.526 91.567,17.526 96.266,17.526 96.266,11.43 89.789,11.43
  text "GND" at 30.353,143.764 h3
  text "OUT+" at 67.564,143.764 h3
  text "Rev. E2" at 107.442,61.849 h2 r90
  text "IN" at 40.259,52.451 h1.52 r90
  text "OUT" at 46.355,50.8 h1.52 r90
  text "IMON" at 52.578,49.53 h1.52 r90
  text "MODE" at 34.671,49.276 h1.52 r90
  text "SYNC" at 42.545,47.498 h1.52
  text "SDA" at 34.798,42.291 h1.52 r90
  text "SCL" at 37.338,42.291 h1.52 r90
  text "GND" at 39.878,42.291 h1.52 r90
  text "I2C" at 34.671,36.703 h1.52
  text "FAULT" at 42.545,36.576 h1.52
  text "EN2 EN1" at 51.181,36.576 h1.52
  text "IN+" at 10.795,36.144 h3
  text "PMP31263" at 108.458,12.446 h5 r90
  text "DISABLE" at 29.21,11.43 h1.52
  text "GND" at 20.955,2.032 h3
Outline:
  the board outline again, w0.254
